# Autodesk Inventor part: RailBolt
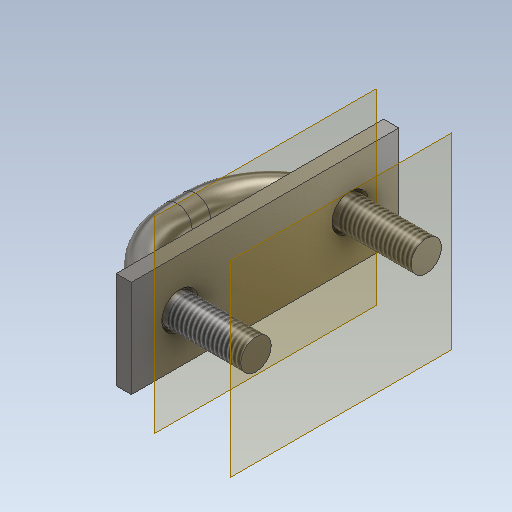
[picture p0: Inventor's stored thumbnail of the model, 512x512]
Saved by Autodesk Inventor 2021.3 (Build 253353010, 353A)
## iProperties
Created: 2019-06
Part Number: RailBolt
Material: Steel, Galvanized
Document SubType Name: Modeling
Designer: u1426
Density: 7.85 g/cm^3
Appearance: Galvanized
Author: u1426
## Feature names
1. Sweep1
2. Extrusion8
3. Hole2
## Parameters: sa_0 = 4 mm, d108 = 88.9 mm, d110 = 80.9625 mm, d111 = 39.6875 mm, d112 = 80.9625 mm, d113 = 15.875 mm, d114 = 0, d115 = 0, d116 = 38.1 mm, d117 = 0, d118 = 38.1 mm, d119 = 0, d120 = -39.6875 mm, d121 = 139.7 mm, d122 = 50.8 mm, d123 = 139.7 mm, d124 = 7.9375 mm, d125 = 0, d126 = 19.05 mm, d127 = 19.05 mm, d128 = 9.525 mm, d129 = 6.35 mm, d130 = 82 deg, d131 = 25.4 mm, d132 = 118 deg, d133 = 25.4 mm, d134 = 25.4 mm, d135 = 25.4 mm, d136 = 25.4 mm
